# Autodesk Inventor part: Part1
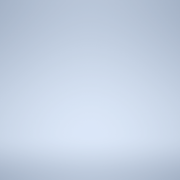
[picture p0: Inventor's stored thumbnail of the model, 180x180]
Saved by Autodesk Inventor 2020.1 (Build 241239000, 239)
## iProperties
Created: 2019-09
Part Number: Part1
Material: Generic
Document SubType Name: Modeling
Designer: Synergysoft Dell02
Density: 1 g/cm^3
Appearance: Default
Author: Synergysoft Dell02
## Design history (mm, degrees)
